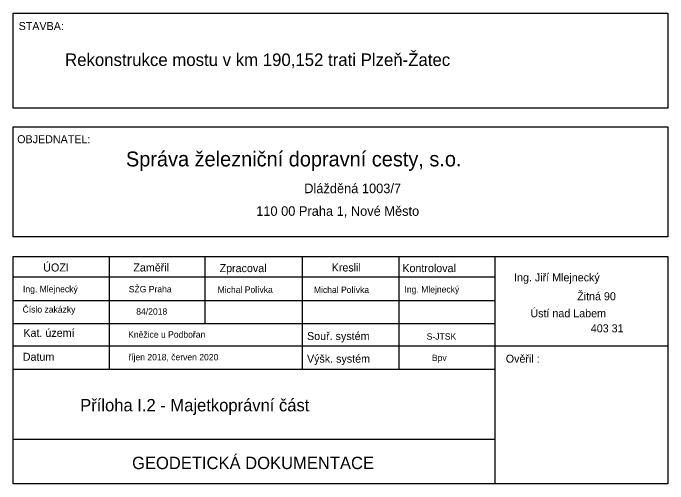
# Model space of a CAD drawing. Extents: x -879530 to -879371, y -1019242 to -1019127.
import ezdxf

# ---------------------------------------------------------------- set-up
doc = ezdxf.new("R2010")
doc.units = 0
doc.layers.add('LEGENDA', color=7, linetype='Continuous')
doc.layers.add('tabulka', color=7, linetype='Continuous')

msp = doc.modelspace()

# ---------------------------------------------------------------- linework, layer by layer
at = {"layer": 'tabulka'}
for p, q in [((-879530.09, -1019186.45), (-879371.44, -1019186.45)), ((-879506.8, -1019186.45), (-879506.8, -1019213.77)), ((-879483.66, -1019186.45), (-879483.66, -1019202.65)), ((-879460.06, -1019186.45), (-879460.06, -1019213.77)), ((-879436.61, -1019186.45), (-879436.61, -1019213.77)), ((-879413.31, -1019241.58), (-879413.31, -1019186.45)), ((-879530.09, -1019191.36), (-879413.31, -1019191.36)), ((-879530.09, -1019197.07), (-879413.31, -1019197.07)), ((-879530.09, -1019202.65), (-879413.31, -1019202.65)), ((-879530.09, -1019208.07), (-879371.44, -1019208.07)), ((-879530.09, -1019213.77), (-879413.31, -1019213.77)), ((-879530.09, -1019230.76), (-879413.31, -1019230.76))]:
    msp.add_line(p, q, dxfattribs=at)
for points in [[(-879530.09, -1019127.36), (-879371.44, -1019127.36), (-879371.44, -1019150.43), (-879530.09, -1019150.43)], [(-879530.09, -1019154.95), (-879371.44, -1019154.95), (-879371.44, -1019181.64), (-879530.09, -1019181.64)]]:
    msp.add_lwpolyline(points, close=True, dxfattribs=at)
msp.add_lwpolyline([(-879371.44, -1019186.45), (-879371.44, -1019241.58), (-879530.09, -1019241.58), (-879530.09, -1019186.45)], dxfattribs=at)

# ---------------------------------------------------------------- texts
at = {"layer": 'LEGENDA'}
msp.add_text('Rekonstrukce mostu v km 190,152 trati Plzeň-Žatec', height=3.04, dxfattribs=at).set_placement((-879517.5, -1019140.2))
at = {"layer": 'tabulka'}
for s, height, p in [('STAVBA:', 1.94, (-879528.75, -1019131.47)), ('OBJEDNATEL:', 1.94, (-879529.1, -1019158.93)), ('Správa železniční dopravní cesty, s.o.', 3.61, (-879502.75, -1019164.56)), ('Dlážděná 1003/7', 2.32, (-879459.55, -1019171.05)), ('110 00 Praha 1, Nové Město', 2.32, (-879471.19, -1019176.55)), ('ÚOZI', 1.94, (-879522.79, -1019190.05)), ('Zaměřil', 1.94, (-879500.95, -1019190.05)), ('Zpracoval', 1.94, (-879480.06, -1019190.2)), ('Kreslil', 1.94, (-879452.9, -1019190.05)), ('Kontroloval', 1.94, (-879435.78, -1019190.2)), ('Ing. Jiří Mlejnecký', 1.94, (-879408.71, -1019192.45)), ('Ing. Mlejnecký', 1.552, (-879527.69, -1019195.08)), ('SŽG Praha', 1.552, (-879502.06, -1019195.11)), ('Michal Polívka', 1.552, (-879480.54, -1019195.23)), ('Michal Polívka', 1.552, (-879457.21, -1019195.27)), ('Ing. Mlejnecký', 1.552, (-879435.26, -1019195.15)), ('Žitná 90', 1.94, (-879393.42, -1019197.03)), ('Číslo zakázky', 1.552, (-879527.79, -1019200.03)), ('84/2018', 1.552, (-879500.25, -1019200.52)), ('Ústí nad Labem', 1.94, (-879404.75, -1019201.15)), ('403 31', 1.94, (-879390.12, -1019204.81)), ('Kat. území', 1.94, (-879527.6, -1019205.91)), ('Kněžice u Podbořan', 1.552, (-879502.22, -1019206.11)), ('Souř. systém', 1.94, (-879458.87, -1019206.68)), ('S-JTSK', 1.552, (-879429.88, -1019206.59)), ('Datum', 1.94, (-879527.74, -1019211.71)), ('říjen 2018, červen 2020', 1.552, (-879502.17, -1019211.6)), ('Výšk. systém', 1.94, (-879458.89, -1019212.17)), ('Bpv', 1.552, (-879428.62, -1019211.78)), ('Ověřil :', 1.94, (-879410.72, -1019212.17)), ('Příloha I.2 - Majetkoprávní část', 3, (-879513.83, -1019223.98)), ('GEODETICKÁ DOKUMENTACE ', 3, (-879501.27, -1019237.99))]:
    msp.add_text(s, height=height, dxfattribs=at).set_placement(p)

doc.saveas('drawing.dxf')
